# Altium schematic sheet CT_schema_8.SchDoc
size 391 x 238 mm
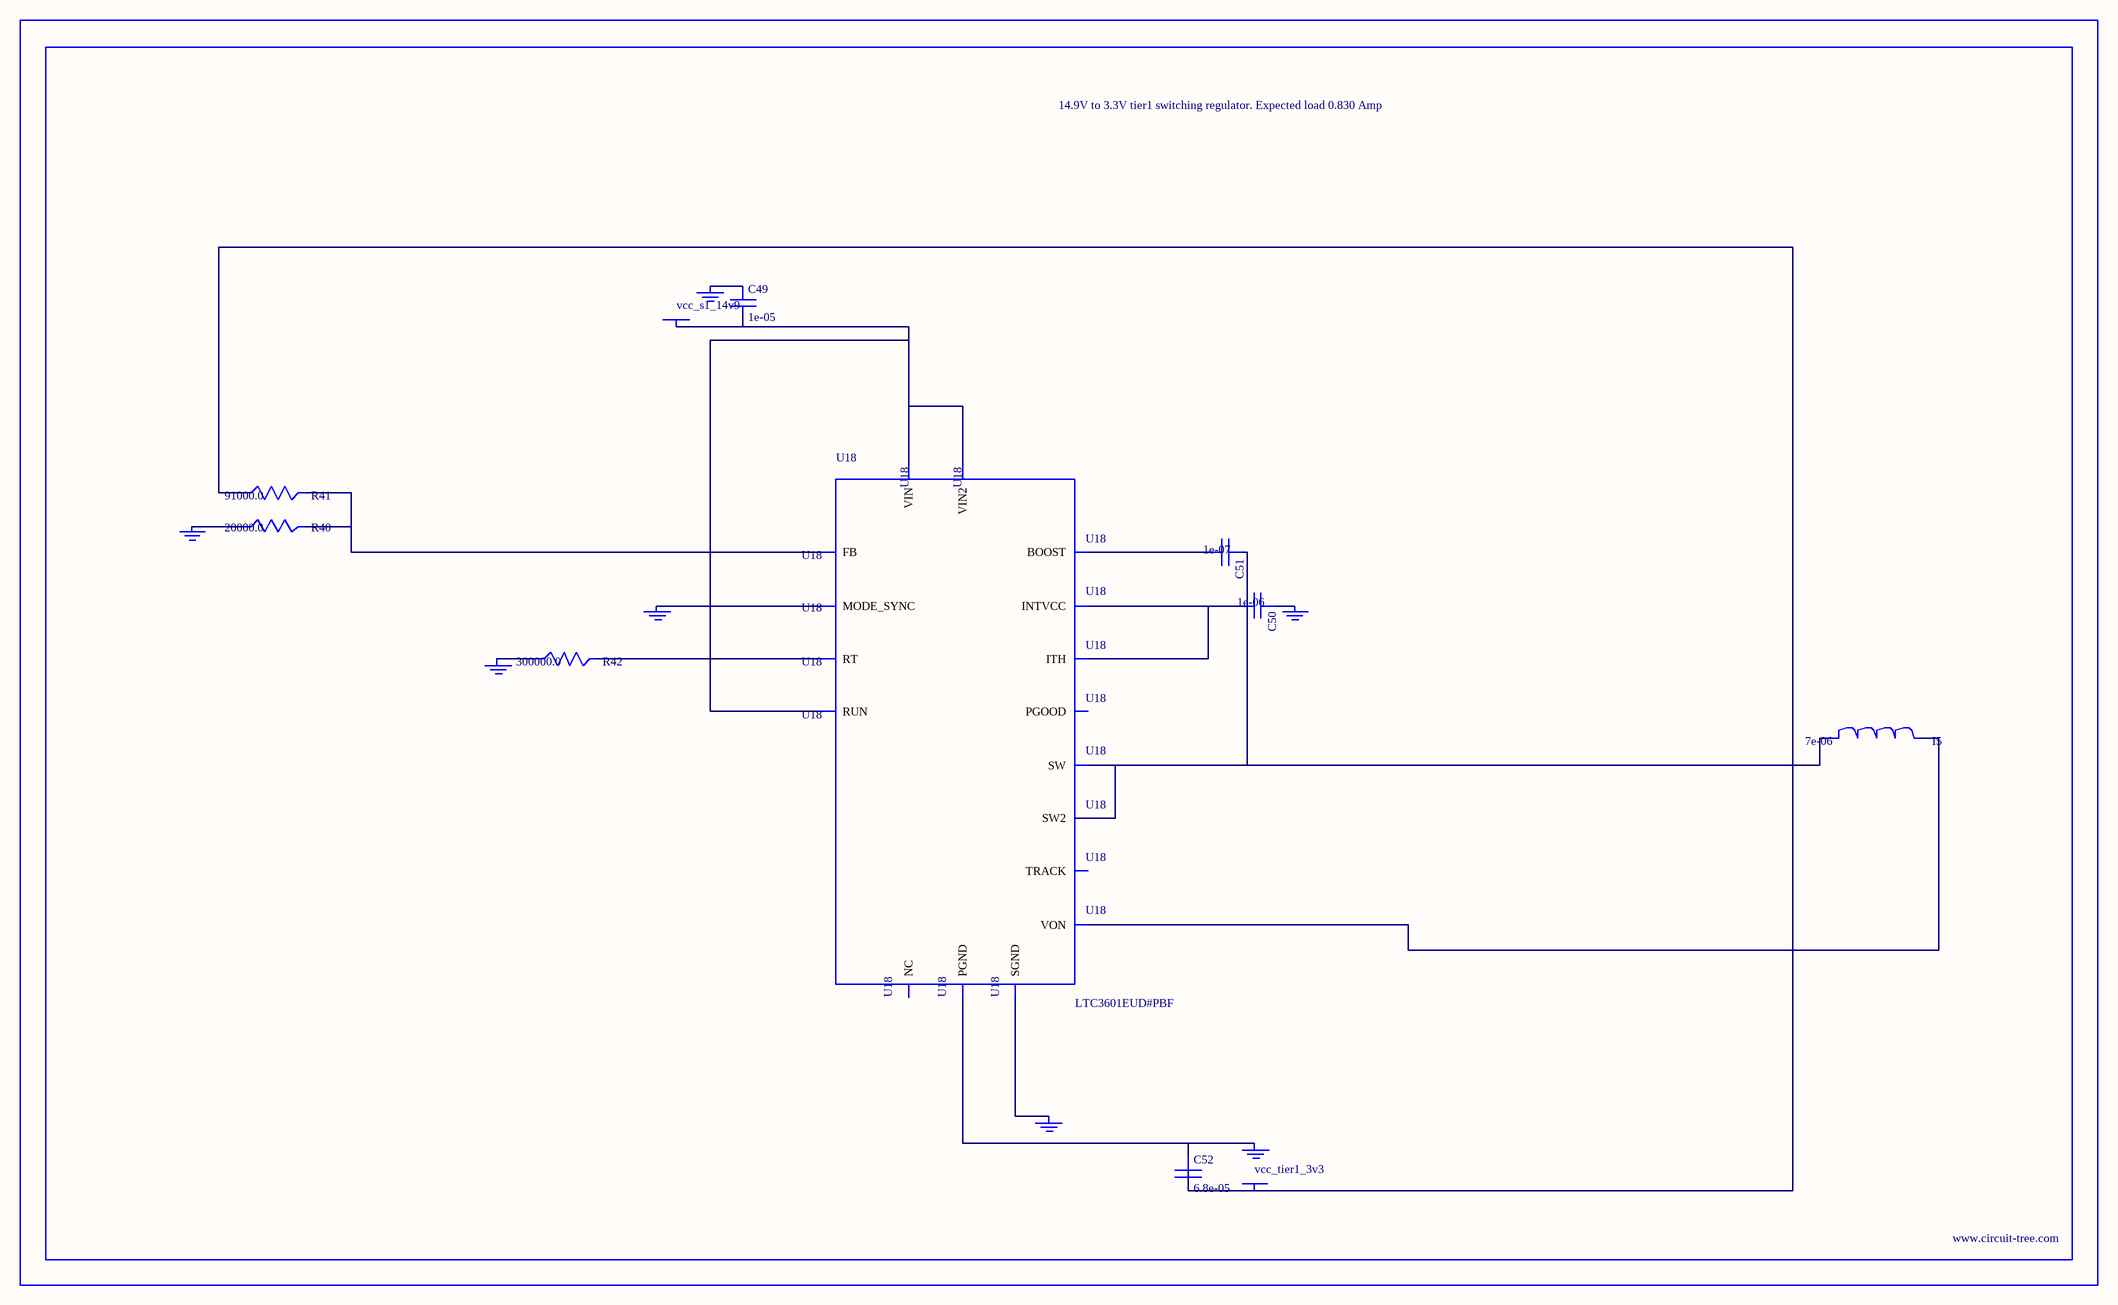
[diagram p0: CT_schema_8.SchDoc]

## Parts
BORDER7  (no value)
C49  1e-05  [C0805]
C50  1e-06  [C0603]
C51  1e-07  [C0402]
C52  6.8e-05  [2220]
GND_INSTANCE_7_0  (no value)
GND_INSTANCE_7_1  (no value)
GND_INSTANCE_7_2  (no value)
GND_INSTANCE_7_3  (no value)
GND_INSTANCE_7_4  (no value)
GND_INSTANCE_7_5  (no value)
GND_INSTANCE_7_6  (no value)
I5  7e-06  [DR1040]
POWER_INSTANCE_7_0  vcc_s1_14v9
POWER_INSTANCE_7_1  vcc_tier1_3v3
R40  20000.0  [R0603]
R41  91000.0  [R0603]
R42  300000.0  [R0603]
U18  LTC3601EUD#PBF  [QFN-16_EP]

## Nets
NetC49_1: C49.1 GND_INSTANCE_7_5.0(GND)
NetC49_2: C49.2 POWER_INSTANCE_7_0.0(PWR) U18.14(RUN) U18.15(VIN) U18.16(VIN2)
NetC50_1: C50.1 GND_INSTANCE_7_1.0(GND)
NetC50_2: C50.2 U18.7(INTVCC) U18.12(ITH)
NetC51_1: C51.1 I5.1 U18.3(SW) U18.4(SW2)
NetC51_2: C51.2 U18.6(BOOST)
NetC52_1: C52.1 GND_INSTANCE_7_6.0(GND) U18.17(PGND)
NetC52_2: C52.2 I5.2 POWER_INSTANCE_7_1.0(PWR) R41.1 U18.8(VON)
NetGND_INSTANCE_7_0_0: GND_INSTANCE_7_0.0(GND) U18.1(MODE_SYNC)
NetGND_INSTANCE_7_2_0: GND_INSTANCE_7_2.0(GND) U18.9(SGND)
NetGND_INSTANCE_7_3_0: GND_INSTANCE_7_3.0(GND) R42.1
NetGND_INSTANCE_7_4_0: GND_INSTANCE_7_4.0(GND) R40.1
NetR40_2: R40.2 R41.2 U18.11(FB)
NetR42_2: R42.2 U18.10(RT)

Not connected (* = marked no-connect by the designer): U18 2(PGOOD) 5(NC) 13(TRACK)

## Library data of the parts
BORDER7 = BORDER_PAGE7
C49 = C0805C106K8RACTU
C50 = C0603C105K3RACTU
C51 = C0402C104K3RACTU
C52 = C5750X5R1A686M
GND_INSTANCE_7_0-GND_INSTANCE_7_6 = GND
I5 = DR1040-7R0-R
POWER_INSTANCE_7_0 POWER_INSTANCE_7_1 = PWR
R40 = RC0603JR-0720KL
R41 = RC0603JR-0791KL
R42 = RC0603JR-07300KL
